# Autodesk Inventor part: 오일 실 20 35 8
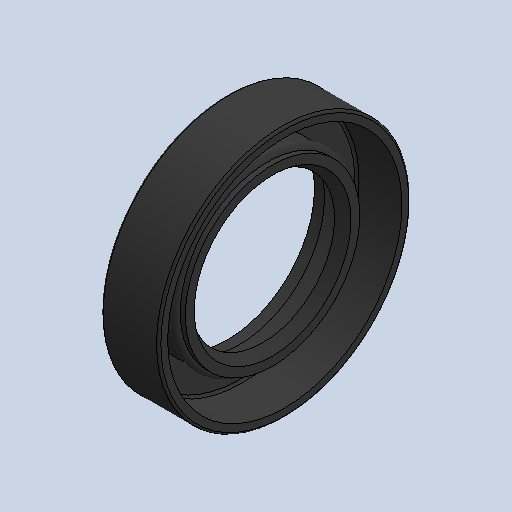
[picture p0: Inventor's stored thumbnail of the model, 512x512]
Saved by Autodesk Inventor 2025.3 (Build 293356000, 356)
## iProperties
Created: 2026-01
Part Number: 오일 실 20 35 8
Material: 고무
Description: 오일-실
Document SubType Name: Modeling
Designer: pc6
Density: 0.93 g/cm^3
Appearance: 기본값
Author: jhkim
Sending System: Autodesk Inventor 2026
Preprocessor: ST-DEVELOPER v20.1
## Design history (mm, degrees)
feature "Solid1"
node "솔리드1"
